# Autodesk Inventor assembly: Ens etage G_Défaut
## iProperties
Shininess: 64.0
Length Units: 11269
Angle Units: 11279
Time Units: 11290
Mass Units: 11283
Length Display Precision: 3
Angle Display Precision: 2
Compacted: True
Created: 2006-01
Part Number: Ens etage G_Défaut
Document SubType Name: Assembly
Designer: Fricot
Density: 0.0
Volumn: 0.0
Area: 0.0
PropertySet Name: Model Information
Control State: 0
Master: False
Checked Out: False
Author: Fricot
